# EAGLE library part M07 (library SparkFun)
Header 7 Standard 7-pin 0.1" header. Use with straight break away headers (SKU : PType-HD), right angle break away headers (PType-HD-RightAngle), swiss pins (PType-30F), machine pins (PType-MP), and female headers (PType-FH). Molex polarized connector foot print use with SKU : Con-Hdr with associated crimp pins and housings.
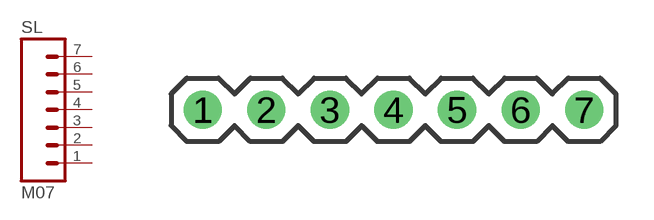
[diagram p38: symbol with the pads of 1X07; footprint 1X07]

Designator prefix SL

## M07  [1X07]
1  1  pas
2  2  pas
3  3  pas
4  4  pas
5  5  pas
6  6  pas
7  7  pas

## Footprint 1X07 (pad centres in mm)
drill 1.016 round: 1 0,0; 2 2.54,0; 3 5.08,0; 4 7.62,0; 5 10.16,0; 6 12.7,0; 7 15.24,0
